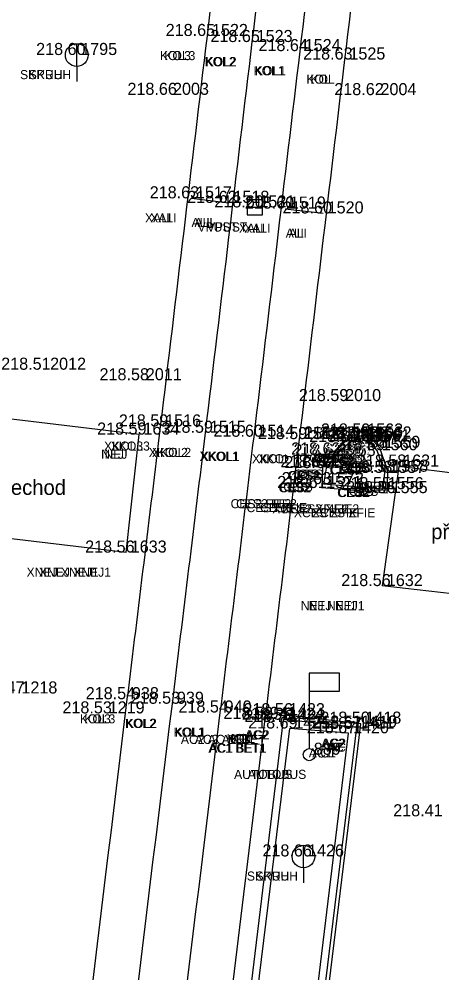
# Model space of a CAD drawing. Extents: x -471047 to -470889, y -1102859 to -1102000.
# Drawn here: x -470963.12 to -470949.12, y -1102410.26 to -1102378.65 of the extents above; entities that cross this region are included whole.
import ezdxf

# ---------------------------------------------------------------- set-up
doc = ezdxf.new("R2010")
doc.units = 0
for name, color, linetype in [('Vrstva 1', 7, 'Continuous'), ('Vrstva 19', 7, 'Continuous'), ('Vrstva 22', 7, 'Continuous'), ('Vrstva 25', 7, 'Continuous'), ('Vrstva 29', 7, 'Continuous'), ('Vrstva 34', 7, 'Continuous'), ('Vrstva 35', 7, 'Continuous'), ('Vrstva 36', 7, 'Continuous'), ('Vrstva 38', 7, 'Continuous'), ('Vrstva 5', 7, 'Continuous'), ('Vrstva 7', 7, 'Continuous'), ('Vrstva 8', 7, 'Continuous'), ('Vrstva 9', 7, 'Continuous')]:
    doc.layers.add(name, color=color, linetype=linetype)

msp = doc.modelspace()

# ---------------------------------------------------------------- linework, layer by layer
at = {"layer": 'Vrstva 1'}
for points in [[(-471040.344, -1102858.385), (-471031.676, -1102846.187), (-471026.357, -1102838.629), (-471023.212, -1102833.975), (-471019.21, -1102827.465), (-471016.861, -1102823.272), (-471013.099, -1102815.912), (-471010.824, -1102810.955), (-471007.329, -1102802.292), (-471005.34, -1102796.515), (-471002.842, -1102787.838), (-471001.3, -1102780.997), (-471000.19, -1102774.713), (-470999.247, -1102768.204), (-470998.794, -1102764.784), (-470997.199, -1102751.812), (-470994.899, -1102732.807), (-470992.551, -1102713.262), (-470990.326, -1102694.887), (-470988.122, -1102676.57), (-470985.812, -1102657.305), (-470983.537, -1102638.407), (-470981.386, -1102620.622), (-470979.843, -1102608.014), (-470976.377, -1102579.253), (-470972.945, -1102550.69), (-470970.475, -1102530.206), (-470967.905, -1102508.801), (-470965.053, -1102485.131), (-470962.734, -1102465.9), (-470960.173, -1102444.812), (-470957.795, -1102425.103), (-470954.965, -1102401.839), (-470953.834, -1102392.574), (-470952.33, -1102379.985), (-470950.744, -1102366.853), (-470948.978, -1102352.106), (-470947.037, -1102335.844), (-470944.949, -1102318.462), (-470944.013, -1102310.745), (-470942.39, -1102297.267), (-470939.519, -1102273.45), (-470937.593, -1102257.43), (-470936.064, -1102244.81), (-470934.114, -1102228.634), (-470931.621, -1102207.856), (-470929.536, -1102190.857), (-470926.572, -1102166.31), (-470924.91, -1102152.663), (-470923.413, -1102140.333), (-470921.923, -1102127.669), (-470921.155, -1102120.084), (-470920.446, -1102109.574), (-470919.912, -1102099.137), (-470919.63, -1102088.981), (-470919.523, -1102081.193), (-470919.563, -1102070.395), (-470919.714, -1102064.236), (-470920.134, -1102054.704), (-470920.462, -1102047.615), (-470920.599, -1102044.52), (-470920.743, -1102041.873), (-470921.125, -1102034.455), (-470921.774, -1102030.337), (-470922.418, -1102027.787), (-470923.734, -1102023.93), (-470924.872, -1102021.434), (-470926.752, -1102018.182), (-470927.953, -1102016.45), (-470929.616, -1102014.424), (-470932.252, -1102011.756), (-470935.111, -1102009.425), (-470938.391, -1102007.371), (-470942.651, -1102005.401)], [(-471041.328, -1102857.18), (-471032.144, -1102844.242), (-471027.583, -1102837.763), (-471024.388, -1102833.028), (-471020.451, -1102826.6), (-471018.089, -1102822.378), (-471014.542, -1102815.445), (-471012.233, -1102810.418), (-471009.247, -1102803.108), (-471006.795, -1102796.098), (-471004.315, -1102787.532), (-471002.782, -1102780.723), (-471001.674, -1102774.458), (-471000.75, -1102768.095), (-471000.28, -1102764.601), (-470998.692, -1102751.741), (-470996.378, -1102732.635), (-470994.028, -1102713.058), (-470991.808, -1102694.749), (-470989.616, -1102676.447), (-470987.284, -1102657.013), (-470985.031, -1102638.272), (-470982.87, -1102620.431), (-470981.334, -1102607.933), (-470977.881, -1102579.263), (-470974.429, -1102550.492), (-470971.964, -1102530.054), (-470969.391, -1102508.607), (-470966.54, -1102484.984), (-470964.231, -1102465.853), (-470961.679, -1102444.752), (-470959.304, -1102425.078), (-470956.455, -1102401.634), (-470955.339, -1102392.489), (-470953.812, -1102379.71), (-470952.249, -1102366.808), (-470950.479, -1102352.023), (-470948.536, -1102335.868), (-470946.426, -1102318.233), (-470945.493, -1102310.531), (-470943.864, -1102297.013), (-470940.984, -1102273.071), (-470939.078, -1102257.195), (-470937.559, -1102244.684), (-470935.592, -1102228.353), (-470933.101, -1102207.653), (-470931.011, -1102190.57), (-470928.046, -1102166.021), (-470926.409, -1102152.578), (-470924.898, -1102140.121), (-470923.427, -1102127.544), (-470922.647, -1102119.826), (-470921.919, -1102109.229), (-470921.42, -1102099.134), (-470921.127, -1102089.016), (-470921.023, -1102081.453), (-470921.061, -1102070.468), (-470921.209, -1102064.314), (-470921.666, -1102053.966), (-470922.156, -1102043.345), (-470922.299, -1102039.934), (-470922.637, -1102034.36), (-470923.091, -1102031.241), (-470923.847, -1102028.247), (-470925.083, -1102024.594), (-470926.222, -1102022.086), (-470928.04, -1102018.943), (-470929.138, -1102017.357), (-470930.929, -1102015.175), (-470933.062, -1102013.049), (-470936.379, -1102010.368), (-470939.169, -1102008.662), (-470942.899, -1102006.906), (-470945.661, -1102005.908)], [(-471043.557, -1102855.955), (-471035.129, -1102844.026), (-471029.872, -1102836.499), (-471026.577, -1102831.578), (-471022.675, -1102825.415), (-471020.123, -1102821.053), (-471016.667, -1102814.59), (-471014.208, -1102809.45), (-471011.177, -1102802.451), (-471008.55, -1102795.333), (-471006.082, -1102787.209), (-471004.464, -1102780.376), (-471003.265, -1102774.167), (-471002.327, -1102767.948), (-471001.636, -1102762.527), (-471000.297, -1102751.605), (-470997.959, -1102732.524), (-470995.602, -1102712.802), (-470993.412, -1102694.623), (-470991.21, -1102676.17), (-470988.891, -1102656.857), (-470986.625, -1102638.083), (-470984.455, -1102620.195), (-470982.936, -1102607.733), (-470979.497, -1102579.223), (-470976.023, -1102550.279), (-470973.554, -1102529.822), (-470970.991, -1102508.497), (-470968.146, -1102484.787), (-470965.835, -1102465.72), (-470963.284, -1102444.529), (-470960.91, -1102424.942), (-470958.043, -1102401.343), (-470956.946, -1102392.356), (-470955.396, -1102379.408), (-470953.851, -1102366.636), (-470952.049, -1102351.733), (-470950.124, -1102335.611), (-470948.034, -1102318.083), (-470947.094, -1102310.328), (-470945.421, -1102296.51), (-470942.58, -1102272.848), (-470940.675, -1102256.948), (-470939.176, -1102244.526), (-470937.187, -1102228.174), (-470934.708, -1102207.467), (-470932.621, -1102190.433), (-470929.634, -1102165.778), (-470928.004, -1102152.415), (-470926.45, -1102139.595), (-470925.003, -1102127.418), (-470924.249, -1102119.695), (-470923.515, -1102109.093), (-470923.018, -1102099.069), (-470922.711, -1102088.911), (-470922.643, -1102081.356), (-470922.797, -1102070.414), (-470923.018, -1102064.454), (-470923.52, -1102053.203), (-470923.823, -1102047.529), (-470924.123, -1102041.506), (-470924.462, -1102037.486), (-470924.934, -1102031.904), (-470925.664, -1102028.672), (-470926.771, -1102025.506), (-470927.959, -1102022.914), (-470929.674, -1102020.028), (-470930.76, -1102018.498), (-470932.447, -1102016.478), (-470935.215, -1102013.816), (-470937.644, -1102011.98), (-470940.381, -1102010.371), (-470943.968, -1102008.669), (-470947.145, -1102007.524), (-470950.874, -1102006.74)], [(-471044.756, -1102855.056), (-471036.376, -1102843.177), (-471031.167, -1102835.741), (-471027.859, -1102830.8), (-471023.934, -1102824.593), (-471021.43, -1102820.312), (-471018.011, -1102813.91), (-471015.536, -1102808.75), (-471012.578, -1102801.897), (-471009.95, -1102794.77), (-471007.561, -1102786.914), (-471005.936, -1102780.074), (-471004.727, -1102773.818), (-471003.828, -1102767.827), (-471003.121, -1102762.345), (-471001.787, -1102751.467), (-470999.446, -1102732.348), (-470997.073, -1102712.539), (-470994.902, -1102694.521), (-470992.696, -1102676.023), (-470990.376, -1102656.68), (-470988.131, -1102638.071), (-470985.947, -1102620.018), (-470984.417, -1102607.512), (-470980.993, -1102579.08), (-470977.514, -1102550.137), (-470975.048, -1102529.649), (-470972.488, -1102508.37), (-470969.618, -1102484.508), (-470967.34, -1102465.669), (-470964.767, -1102444.39), (-470962.402, -1102424.781), (-470959.534, -1102401.193), (-470958.432, -1102392.151), (-470956.883, -1102379.208), (-470955.335, -1102366.424), (-470953.535, -1102351.506), (-470951.606, -1102335.399), (-470949.519, -1102317.94), (-470948.575, -1102310.159), (-470946.889, -1102296.144), (-470944.056, -1102272.618), (-470942.139, -1102256.659), (-470940.657, -1102244.341), (-470938.638, -1102227.749), (-470936.19, -1102207.298), (-470934.102, -1102190.255), (-470931.124, -1102165.639), (-470929.492, -1102152.254), (-470927.915, -1102139.252), (-470926.46, -1102127.103), (-470925.74, -1102119.604), (-470925.012, -1102108.913), (-470924.523, -1102099.054), (-470924.217, -1102088.866), (-470924.148, -1102081.334), (-470924.301, -1102070.391), (-470924.518, -1102064.43), (-470924.97, -1102054.435), (-470925.588, -1102041.569), (-470925.963, -1102035.313), (-470926.405, -1102032.225), (-470927.078, -1102029.198), (-470928.123, -1102026.148), (-470929.318, -1102023.558), (-470930.84, -1102020.97), (-470931.868, -1102019.515), (-470933.443, -1102017.605), (-470936.26, -1102014.885), (-470938.429, -1102013.255), (-470941.213, -1102011.639), (-470944.847, -1102009.927), (-470947.723, -1102008.912), (-470951.444, -1102008.161), (-470954.511, -1102007.931), (-470957.895, -1102008.041)]]:
    msp.add_spline(points, degree=3, dxfattribs=at)
at = {"layer": 'Vrstva 19'}
for p, q in [((-470952.509, -1102400.327), (-470953.509, -1102400.327)), ((-470953.509, -1102400.327), (-470953.509, -1102402.827)), ((-470952.509, -1102400.927), (-470952.509, -1102400.327)), ((-470953.509, -1102400.927), (-470952.509, -1102400.927))]:
    msp.add_line(p, q, dxfattribs=at)
msp.add_circle((-470953.509, -1102403.027), 0.2, dxfattribs=at)
at = {"layer": 'Vrstva 25'}
for p, q in [((-470961.21, -1102380.216), (-470961.21, -1102379.466)), ((-470961.21, -1102380.216), (-470961.21, -1102380.716)), ((-470955.562, -1102384.636), (-470955.562, -1102385.136)), ((-470955.062, -1102384.636), (-470955.562, -1102384.636)), ((-470955.062, -1102385.136), (-470955.062, -1102384.636)), ((-470955.562, -1102384.886), (-470955.062, -1102384.886)), ((-470955.562, -1102385.136), (-470955.062, -1102385.136)), ((-470953.703, -1102406.777), (-470953.703, -1102406.027)), ((-470953.703, -1102406.777), (-470953.703, -1102407.277))]:
    msp.add_line(p, q, dxfattribs=at)
for centre in [(-470961.21, -1102379.841), (-470953.703, -1102406.402)]:
    msp.add_circle(centre, 0.375, dxfattribs=at)
at = {"layer": 'Vrstva 29'}
for p, q in [((-470957.407, -1102384.588), (-470956.168, -1102384.735)), ((-470954.305, -1102384.934), (-470953.055, -1102385.086))]:
    msp.add_line(p, q, dxfattribs=at)
at = {"layer": 'Vrstva 34'}
for p, q in [((-470956.88, -1102379.21), (-470956.88, -1102379.21)), ((-470955.4, -1102379.41), (-470955.4, -1102379.41)), ((-470953.81, -1102379.71), (-470953.81, -1102379.71)), ((-470961.21, -1102379.84), (-470961.21, -1102379.84)), ((-470952.33, -1102379.99), (-470952.33, -1102379.99)), ((-470958.17, -1102381.16), (-470958.17, -1102381.16)), ((-470951.3, -1102381.17), (-470951.3, -1102381.17)), ((-470957.41, -1102384.59), (-470957.41, -1102384.59)), ((-470956.17, -1102384.74), (-470956.17, -1102384.74)), ((-470955.31, -1102384.89), (-470955.31, -1102384.89)), ((-470954.3, -1102384.93), (-470954.3, -1102384.93)), ((-470953.05, -1102385.09), (-470953.05, -1102385.09)), ((-470962.24, -1102390.27), (-470962.24, -1102390.27)), ((-470959.07, -1102390.62), (-470959.07, -1102390.62)), ((-470952.47, -1102391.31), (-470952.47, -1102391.31)), ((-470958.43, -1102392.15), (-470958.43, -1102392.15)), ((-470956.95, -1102392.36), (-470956.95, -1102392.36)), ((-470959.15, -1102392.42), (-470959.15, -1102392.42)), ((-470955.34, -1102392.49), (-470955.34, -1102392.49)), ((-470953.83, -1102392.57), (-470953.83, -1102392.57)), ((-470952.22, -1102392.55), (-470952.22, -1102392.55)), ((-470952.17, -1102392.67), (-470952.17, -1102392.67)), ((-470951.79, -1102392.56), (-470951.79, -1102392.56)), ((-470951.74, -1102392.45), (-470951.74, -1102392.45)), ((-470951.51, -1102392.64), (-470951.51, -1102392.64)), ((-470951.46, -1102392.55), (-470951.46, -1102392.55)), ((-470951.26, -1102392.94), (-470951.26, -1102392.94)), ((-470951.17, -1102392.86), (-470951.17, -1102392.86)), ((-470952.73, -1102393.08), (-470952.73, -1102393.08)), ((-470952.65, -1102393.13), (-470952.65, -1102393.13)), ((-470953.08, -1102393.5), (-470953.08, -1102393.5)), ((-470952.95, -1102393.53), (-470952.95, -1102393.53)), ((-470950.91, -1102393.65), (-470950.91, -1102393.65)), ((-470950.55, -1102393.48), (-470950.55, -1102393.48)), ((-470951.01, -1102393.69), (-470951.01, -1102393.69)), ((-470953.1, -1102394.19), (-470953.1, -1102394.19)), ((-470953.04, -1102394.06), (-470953.04, -1102394.06)), ((-470951.06, -1102394.23), (-470951.06, -1102394.23)), ((-470950.93, -1102394.36), (-470950.93, -1102394.36)), ((-470959.57, -1102396.33), (-470959.57, -1102396.33)), ((-470951.09, -1102397.44), (-470951.09, -1102397.44)), ((-470959.53, -1102401.19), (-470959.53, -1102401.19)), ((-470958.04, -1102401.34), (-470958.04, -1102401.34)), ((-470960.3, -1102401.66), (-470960.3, -1102401.66)), ((-470956.46, -1102401.63), (-470956.46, -1102401.63)), ((-470954.97, -1102401.84), (-470954.97, -1102401.84)), ((-470954.36, -1102401.87), (-470954.36, -1102401.87)), ((-470954.33, -1102401.72), (-470954.33, -1102401.72)), ((-470954.31, -1102401.94), (-470954.31, -1102401.94)), ((-470954.15, -1102402.16), (-470954.15, -1102402.16)), ((-470952.03, -1102402.17), (-470952.03, -1102402.17)), ((-470951.94, -1102402.13), (-470951.94, -1102402.13)), ((-470951.8, -1102402), (-470951.8, -1102402)), ((-470952.21, -1102402.32), (-470952.21, -1102402.32)), ((-470953.51, -1102403.03), (-470953.51, -1102403.03)), ((-470949.26, -1102405.07), (-470949.26, -1102405.07)), ((-470953.7, -1102406.4), (-470953.7, -1102406.4))]:
    msp.add_line(p, q, dxfattribs=at)
at = {"layer": 'Vrstva 5'}
for p, q in [((-470952.175, -1102392.669), (-470952.652, -1102393.133)), ((-470951.789, -1102392.556), (-470952.175, -1102392.669)), ((-470951.513, -1102392.644), (-470951.789, -1102392.556)), ((-470951.257, -1102392.944), (-470951.513, -1102392.644)), ((-470951.009, -1102393.691), (-470951.257, -1102392.944)), ((-470952.652, -1102393.133), (-470952.945, -1102393.531)), ((-470952.945, -1102393.531), (-470953.037, -1102394.063)), ((-470951.063, -1102394.229), (-470951.009, -1102393.691)), ((-470951.063, -1102394.229), (-470953.037, -1102394.063)), ((-470954.325, -1102401.716), (-470954.359, -1102401.865)), ((-470951.798, -1102402.005), (-470954.325, -1102401.716)), ((-470954.625, -1102425.158), (-470951.798, -1102402.005))]:
    msp.add_line(p, q, dxfattribs=at)
at = {"layer": 'Vrstva 7'}
for p, q in [((-470956.892, -1102424.551), (-470954.154, -1102402.157)), ((-470952.206, -1102402.318), (-470954.154, -1102402.157)), ((-470954.975, -1102425.139), (-470952.206, -1102402.318))]:
    msp.add_line(p, q, dxfattribs=at)
at = {"layer": 'Vrstva 8'}
for p, q in [((-470952.219, -1102392.551), (-470952.733, -1102393.077)), ((-470951.74, -1102392.451), (-470952.219, -1102392.551)), ((-470951.463, -1102392.555), (-470951.74, -1102392.451)), ((-470951.169, -1102392.861), (-470951.463, -1102392.555)), ((-470950.912, -1102393.653), (-470951.169, -1102392.861)), ((-470952.733, -1102393.077), (-470953.075, -1102393.5)), ((-470953.075, -1102393.5), (-470953.099, -1102394.185)), ((-470950.932, -1102394.36), (-470950.912, -1102393.653)), ((-470950.932, -1102394.36), (-470953.099, -1102394.185)), ((-470957.114, -1102424.473), (-470954.359, -1102401.865)), ((-470951.937, -1102402.126), (-470954.359, -1102401.865)), ((-470954.752, -1102425.107), (-470951.937, -1102402.126))]:
    msp.add_line(p, q, dxfattribs=at)
at = {"layer": 'Vrstva 9'}
for p, q in [((-470959.145, -1102392.417), (-470964.68, -1102391.755)), ((-470959.569, -1102396.325), (-470959.145, -1102392.417)), ((-470950.548, -1102393.482), (-470951.095, -1102397.436)), ((-470944.791, -1102394.172), (-470950.548, -1102393.482)), ((-470959.569, -1102396.325), (-470965.118, -1102395.662)), ((-470945.189, -1102398.097), (-470951.095, -1102397.436))]:
    msp.add_line(p, q, dxfattribs=at)

# ---------------------------------------------------------------- texts
at = {"layer": 'Vrstva 22'}
for p in [(-470963.982, -1102394.419), (-470949.472, -1102395.886)]:
    msp.add_text('přechod', height=0.5, dxfattribs=at).set_placement(p)
at = {"layer": 'Vrstva 35'}
for s, p in [('KOL3', (-470958.455, -1102380.01)), ('KOL3', (-470958.308, -1102380.01)), ('KOL2', (-470956.975, -1102380.21)), ('KOL2', (-470956.941, -1102380.21)), ('SKRUH', (-470963.085, -1102380.64)), ('SKRUH', (-470962.799, -1102380.64)), ('KOL1', (-470955.352, -1102380.51)), ('KOL1', (-470955.31, -1102380.51)), ('KOL', (-470953.605, -1102380.79)), ('KOL', (-470953.469, -1102380.79)), ('XALI', (-470958.948, -1102385.39)), ('XALI', (-470958.774, -1102385.39)), ('ALI', (-470957.408, -1102385.54)), ('ALI', (-470957.309, -1102385.54)), ('VPUST', (-470957.21, -1102385.69)), ('VPUST', (-470956.899, -1102385.69)), ('XALI', (-470955.838, -1102385.73)), ('XALI', (-470955.664, -1102385.73)), ('ALI', (-470954.288, -1102385.89)), ('ALI', (-470954.189, -1102385.89)), ('XKOL3', (-470960.305, -1102392.95)), ('XKOL3', (-470960.083, -1102392.95)), ('NEJ', (-470960.4, -1102393.22)), ('NEJ', (-470960.289, -1102393.22)), ('XKOL2', (-470958.825, -1102393.16)), ('XKOL2', (-470958.716, -1102393.16)), ('XKOL1', (-470957.14, -1102393.29)), ('XKOL1', (-470957.107, -1102393.29)), ('CES', (-470953.029, -1102393.25)), ('CES', (-470952.879, -1102393.25)), ('XKOL', (-470955.405, -1102393.37)), ('XKOL', (-470955.194, -1102393.37)), ('CES2', (-470953.745, -1102393.47)), ('CES2', (-470953.711, -1102393.47)), ('CES', (-470953.509, -1102393.35)), ('CES2', (-470953.365, -1102393.36)), ('CES', (-470953.359, -1102393.35)), ('CES2', (-470953.331, -1102393.36)), ('CES2', (-470953.085, -1102393.44)), ('CES2', (-470953.051, -1102393.44)), ('CES', (-470952.749, -1102393.35)), ('CES', (-470952.599, -1102393.35)), ('CES2', (-470954.225, -1102393.93)), ('CES2', (-470954.191, -1102393.93)), ('CES', (-470954.019, -1102393.88)), ('CES', (-470953.869, -1102393.88)), ('CES2', (-470952.835, -1102393.74)), ('CES2', (-470952.801, -1102393.74)), ('CES', (-470952.459, -1102393.66)), ('CES', (-470952.309, -1102393.66)), ('CES2', (-470954.525, -1102394.33)), ('CES2', (-470954.491, -1102394.33)), ('CES', (-470954.369, -1102394.3)), ('CES', (-470954.219, -1102394.3)), ('CES2', (-470952.585, -1102394.49)), ('CES2', (-470952.551, -1102394.49)), ('CES', (-470952.199, -1102394.45)), ('CES', (-470952.049, -1102394.45)), ('NEJ', (-470951.8, -1102394.28)), ('NEJ', (-470951.689, -1102394.28)), ('CES2 FIE2', (-470956.115, -1102394.86)), ('CES2 FIE2', (-470955.931, -1102394.86)), ('CES FIE', (-470955.588, -1102394.99)), ('CES FIE', (-470955.139, -1102394.99)), ('XCES2 XFIE2', (-470954.735, -1102395.03)), ('XCES2 XFIE2', (-470954.401, -1102395.03)), ('XCES XFIE', (-470954.018, -1102395.16)), ('XCES XFIE', (-470953.419, -1102395.16)), ('XNEJ XNEJ1', (-470962.87, -1102397.13)), ('XNEJ XNEJ1', (-470962.462, -1102397.13)), ('NEJ NEJ1', (-470953.79, -1102398.24)), ('NEJ NEJ1', (-470953.532, -1102398.24)), ('KOL3', (-470961.105, -1102401.99)), ('KOL3', (-470960.958, -1102401.99)), ('KOL2', (-470959.615, -1102402.14)), ('KOL2', (-470959.581, -1102402.14)), ('KOL1', (-470958.002, -1102402.43)), ('KOL1', (-470957.96, -1102402.43)), ('AC2 AC BET', (-470957.76, -1102402.67)), ('AC2 AC BET', (-470957.3, -1102402.67)), ('KOL', (-470956.245, -1102402.64)), ('KOL', (-470956.109, -1102402.64)), ('AC2', (-470955.646, -1102402.52)), ('AC2', (-470955.605, -1102402.52)), ('AC2', (-470953.116, -1102402.8)), ('AC2', (-470953.075, -1102402.8)), ('AC1 BET1', (-470956.85, -1102402.96)), ('AC1 BET1', (-470956.817, -1102402.96)), ('AC1', (-470953.527, -1102403.12)), ('AC1', (-470953.41, -1102403.12)), ('AC', (-470952.929, -1102402.93)), ('AC', (-470952.854, -1102402.93)), ('AUTOBUS', (-470955.999, -1102403.83)), ('AUTOBUS', (-470955.549, -1102403.83)), ('SKRUH', (-470955.575, -1102407.2)), ('SKRUH', (-470955.289, -1102407.2))]:
    msp.add_text(s, height=0.3, dxfattribs=at).set_placement(p)
at = {"layer": 'Vrstva 36'}
for s, p in [(' 1522', (-470956.88, -1102379.21)), (' 1523', (-470955.4, -1102379.41)), (' 1795', (-470961.21, -1102379.84)), (' 1524', (-470953.81, -1102379.71)), (' 1525', (-470952.33, -1102379.99)), (' 2003', (-470958.17, -1102381.16)), (' 2004', (-470951.3, -1102381.17)), (' 1517', (-470957.41, -1102384.59)), (' 1518', (-470956.17, -1102384.74)), (' 1521', (-470955.31, -1102384.89)), (' 1519', (-470954.3, -1102384.93)), (' 1520', (-470953.05, -1102385.09)), (' 2012', (-470962.24, -1102390.27)), (' 2011', (-470959.07, -1102390.62)), (' 2010', (-470952.47, -1102391.31)), (' 1516', (-470958.43, -1102392.15)), (' 1634', (-470959.15, -1102392.42)), (' 1515', (-470956.95, -1102392.36)), (' 1563', (-470951.74, -1102392.45)), (' 1514', (-470955.34, -1102392.49)), (' 1513', (-470953.83, -1102392.57)), (' 1566', (-470952.22, -1102392.55)), (' 1565', (-470952.17, -1102392.67)), (' 1564', (-470951.79, -1102392.56)), (' 1561', (-470951.51, -1102392.64)), (' 1562', (-470951.46, -1102392.55)), (' 1567', (-470952.73, -1102393.08)), (' 1560', (-470951.26, -1102392.94)), (' 1559', (-470951.17, -1102392.86)), (' 1568', (-470952.65, -1102393.13)), (' 1570', (-470953.08, -1102393.5)), (' 1569', (-470952.95, -1102393.53)), (' 1557', (-470951.01, -1102393.69)), (' 1558', (-470950.91, -1102393.65)), (' 1631', (-470950.55, -1102393.48)), (' 1572', (-470953.04, -1102394.06)), (' 1571', (-470953.1, -1102394.19)), (' 1556', (-470951.06, -1102394.23)), (' 1555', (-470950.93, -1102394.36)), (' 1633', (-470959.57, -1102396.33)), (' 1632', (-470951.09, -1102397.44)), (' 1218', (-470963.19, -1102401)), (' 938', (-470959.53, -1102401.19)), (' 939', (-470958.04, -1102401.34)), (' 940', (-470956.46, -1102401.63)), (' 1219', (-470960.3, -1102401.66)), (' 941', (-470954.97, -1102401.84)), (' 1424', (-470954.36, -1102401.87)), (' 1423', (-470954.33, -1102401.72)), (' 1422', (-470954.31, -1102401.94)), (' 1425', (-470954.15, -1102402.16)), (' 1421', (-470952.03, -1102402.17)), (' 1419', (-470951.94, -1102402.13)), (' 1418', (-470951.8, -1102402)), (' 1420', (-470952.21, -1102402.32)), (' 889', (-470953.51, -1102403.03)), (' 1426', (-470953.7, -1102406.4))]:
    msp.add_text(s, height=0.4, dxfattribs=at).set_placement(p)
at = {"layer": 'Vrstva 38'}
for s, p in [('218.65 ', (-470958.264, -1102379.21)), ('218.65 ', (-470956.784, -1102379.41)), ('218.60 ', (-470962.553, -1102379.84)), ('218.64 ', (-470955.192, -1102379.71)), ('218.63 ', (-470953.713, -1102379.99)), ('218.66 ', (-470959.53, -1102381.16)), ('218.62 ', (-470952.681, -1102381.17)), ('218.63 ', (-470958.793, -1102384.59)), ('218.62 ', (-470957.551, -1102384.74)), ('218.60 ', (-470956.653, -1102384.89)), ('218.60 ', (-470955.643, -1102384.93)), ('218.60 ', (-470954.393, -1102385.09)), ('218.51 ', (-470963.71, -1102390.27)), ('218.58 ', (-470960.454, -1102390.62)), ('218.59 ', (-470953.854, -1102391.31)), ('218.59 ', (-470959.814, -1102392.15)), ('218.59 ', (-470960.534, -1102392.42)), ('218.59 ', (-470958.334, -1102392.36)), ('218.59 ', (-470953.124, -1102392.45)), ('218.60 ', (-470956.683, -1102392.49)), ('218.59 ', (-470955.214, -1102392.57)), ('218.61 ', (-470953.69, -1102392.55)), ('218.60 ', (-470953.513, -1102392.67)), ('218.59 ', (-470953.174, -1102392.56)), ('218.60 ', (-470952.853, -1102392.64)), ('218.58 ', (-470952.844, -1102392.55)), ('218.62 ', (-470954.111, -1102393.08)), ('218.59 ', (-470952.644, -1102392.94)), ('218.58 ', (-470952.554, -1102392.86)), ('218.62 ', (-470954.031, -1102393.13)), ('218.62 ', (-470954.461, -1102393.5)), ('218.63 ', (-470954.333, -1102393.53)), ('218.58 ', (-470952.394, -1102393.69)), ('218.58 ', (-470952.294, -1102393.65)), ('218.58 ', (-470951.934, -1102393.48)), ('218.63 ', (-470954.423, -1102394.06)), ('218.61 ', (-470954.57, -1102394.19)), ('218.55 ', (-470952.444, -1102394.23)), ('218.56 ', (-470952.29, -1102394.36)), ('218.56 ', (-470960.93, -1102396.33)), ('218.56 ', (-470952.45, -1102397.44)), ('218.47 ', (-470964.573, -1102401)), ('218.54 ', (-470960.912, -1102401.19)), ('218.53 ', (-470959.423, -1102401.34)), ('218.54 ', (-470957.842, -1102401.63)), ('218.53 ', (-470961.683, -1102401.66)), ('218.53 ', (-470956.353, -1102401.84)), ('218.55 ', (-470955.744, -1102401.87)), ('218.56 ', (-470955.69, -1102401.72)), ('218.70 ', (-470955.653, -1102401.94)), ('218.69 ', (-470955.534, -1102402.16)), ('218.67 ', (-470953.413, -1102402.17)), ('218.51 ', (-470953.41, -1102402.13)), ('218.50 ', (-470953.143, -1102402)), ('218.67 ', (-470953.593, -1102402.32)), ('218.41 ', (-470950.73, -1102405.07)), ('218.66 ', (-470955.06, -1102406.4))]:
    msp.add_text(s, height=0.4, dxfattribs=at).set_placement(p)

doc.saveas('drawing.dxf')
